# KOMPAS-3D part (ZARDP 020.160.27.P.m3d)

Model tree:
1. Плоскость XY
2. Плоскость ZX
3. Плоскость ZY
4. Ось X
5. Ось Y
6. Ось Z
7. Начало координат
8. Булева операция:1
9. Булева операция:2
10. Булева операция:3
11. Булева операция:4
